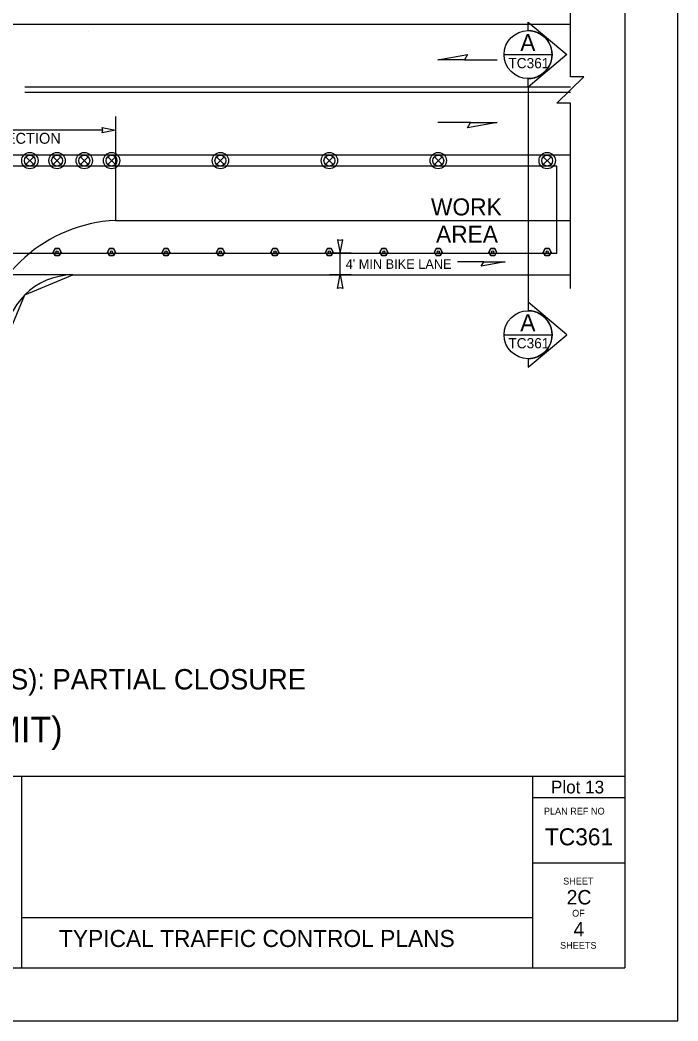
# Model space of a CAD drawing. Extents: x 99958 to 100176, y 99935 to 100011.
# Drawn here: x 100052.2 to 100056.06, y 99969.69 to 99975.57 of the extents above; entities that cross this region are included whole.
import ezdxf

# ---------------------------------------------------------------- set-up
doc = ezdxf.new("R2010")
doc.units = 0
for name, color, linetype in [('RD_ED_ShoulderPavedEdge', 7, 'Continuous'), ('RD_MK_LineDblYellowCenter', 7, 'Continuous'), ('RD_MK_LineEdgeWhite', 7, 'Continuous'), ('RD_MK_LineEdgeYellow', 7, 'Continuous'), ('RD_MK_LineLane', 7, 'Continuous'), ('SH_DE_DetailHeading1Text', 7, 'Continuous'), ('SH_DE_DetailHeading2Text', 7, 'Continuous'), ('SH_GI_PlotLimits', 7, 'Continuous'), ('SH_GI_SheetBorder', 7, 'Continuous'), ('SH_GI_SheetLocationText', 7, 'Continuous'), ('SH_GI_SheetTextInCells', 7, 'Continuous'), ('SH_GI_TitleBlockText', 7, 'Continuous'), ('SH_TI_WZSectionCut', 7, 'Continuous'), ('TR_WZ_TrafficSafetyDrum', 7, 'Continuous'), ('TR_WZ_TubularMarker', 7, 'Continuous'), ('TR_WZ_WorkAreaLabel', 7, 'Continuous'), ('TR_WZ_WorkZoneDetails', 7, 'Continuous'), ('TR_WZ_WorkZoneTextCurrent', 7, 'Continuous')]:
    doc.layers.add(name, color=color, linetype=linetype)

msp = doc.modelspace()

# ---------------------------------------------------------------- linework, layer by layer
at = {"layer": 'RD_ED_ShoulderPavedEdge'}
msp.add_line((100052.5069, 99974.0724), (100055.43, 99974.0724), dxfattribs=at)
msp.add_arc((100052.5069, 99973.6724), 0.4, 90, 180, dxfattribs=at)
at = {"layer": 'RD_MK_LineDblYellowCenter'}
for p, q in [((100055.43, 99975.1764), (100052.2245, 99975.1764)), ((100055.43, 99975.1444), (100052.2245, 99975.1444))]:
    msp.add_line(p, q, dxfattribs=at)
at = {"layer": 'RD_MK_LineEdgeWhite'}
msp.add_arc((100052.7969, 99973.5319), 0.8615, 92.65548, 170.6116, dxfattribs=at)
at = {"layer": 'RD_MK_LineEdgeYellow'}
msp.add_line((100052.7569, 99974.3924), (100055.43, 99974.3924), dxfattribs=at)
at = {"layer": 'RD_MK_LineLane'}
for points in [[(100055.43, 99975.5444), (100048.195, 99975.5444)], [(100055.43, 99974.7764), (100048.195, 99974.7764)]]:
    msp.add_lwpolyline(points, dxfattribs=at)
at = {"layer": 'SH_GI_PlotLimits'}
msp.add_lwpolyline([(100039.0625, 99969.6875), (100056.0625, 99969.6875), (100056.0625, 99980.6875), (100039.0625, 99980.6875)], close=True, dxfattribs=at)
at = {"layer": 'SH_GI_SheetBorder'}
for p, q in [((100055.75, 99980.375), (100055.75, 99970)), ((100040, 99971.1259), (100055.75, 99971.1259)), ((100052.2055, 99971.1259), (100052.2055, 99970)), ((100055.2079, 99971.1259), (100055.2079, 99970)), ((100055.2079, 99971.0008), (100055.75, 99971.0008)), ((100055.2079, 99970.6176), (100055.75, 99970.6176)), ((100052.2055, 99970.2955), (100055.2079, 99970.2955)), ((100040, 99970), (100055.75, 99970))]:
    msp.add_line(p, q, dxfattribs=at)
at = {"layer": 'SH_TI_WZSectionCut'}
for p, q in [((100055.1819, 99975.5088), (100055.1819, 99975.5587)), ((100055.1819, 99975.5587), (100055.41, 99975.3676)), ((100055.41, 99975.3676), (100055.1819, 99975.1764)), ((100055.1819, 99975.1764), (100055.1819, 99975.2264)), ((100055.1819, 99975.1764), (100055.1819, 99973.9125)), ((100055.1819, 99973.9125), (100055.1819, 99973.8625)), ((100055.41, 99973.7213), (100055.1819, 99973.9125)), ((100055.1819, 99973.5302), (100055.41, 99973.7213)), ((100055.1819, 99973.5801), (100055.1819, 99973.5302))]:
    msp.add_line(p, q, dxfattribs=at)
for points in [[(100055.0406, 99975.3676), (100055.3231, 99975.3676)], [(100055.0406, 99973.7213), (100055.3231, 99973.7213)]]:
    msp.add_lwpolyline(points, dxfattribs=at)
for centre in [(100055.1819, 99975.3676), (100055.1819, 99973.7213)]:
    msp.add_circle(centre, 0.1412, dxfattribs=at)
for centre in [(100055.1819, 99975.3676), (100055.1819, 99973.7213)]:
    msp.add_arc(centre, 0.1412, 269.99779, 90.00221, dxfattribs=at)
at = {"layer": 'TR_WZ_TrafficSafetyDrum'}
for p, q in [((100052.2313, 99974.7671), (100052.2765, 99974.7218)), ((100052.2765, 99974.7671), (100052.2313, 99974.7218)), ((100052.3913, 99974.7671), (100052.4365, 99974.7218)), ((100052.4365, 99974.7671), (100052.3913, 99974.7218)), ((100052.5513, 99974.7671), (100052.5965, 99974.7218)), ((100052.5965, 99974.7671), (100052.5513, 99974.7218)), ((100052.7113, 99974.7671), (100052.7565, 99974.7218)), ((100052.7565, 99974.7671), (100052.7113, 99974.7218)), ((100053.3513, 99974.7671), (100053.3965, 99974.7218)), ((100053.3965, 99974.7671), (100053.3513, 99974.7218)), ((100053.9913, 99974.7671), (100054.0365, 99974.7218)), ((100054.0365, 99974.7671), (100053.9913, 99974.7218)), ((100054.6313, 99974.7671), (100054.6765, 99974.7218)), ((100054.6765, 99974.7671), (100054.6313, 99974.7218)), ((100055.2713, 99974.7671), (100055.3165, 99974.7218)), ((100055.3165, 99974.7671), (100055.2713, 99974.7218))]:
    msp.add_line(p, q, dxfattribs=at)
for centre, radius in [((100052.2539, 99974.7445), 0.048), ((100052.2539, 99974.7445), 0.048), ((100052.2539, 99974.7445), 0.032), ((100052.4139, 99974.7445), 0.048), ((100052.4139, 99974.7445), 0.048), ((100052.4139, 99974.7445), 0.032), ((100052.5739, 99974.7445), 0.048), ((100052.5739, 99974.7445), 0.048), ((100052.5739, 99974.7445), 0.032), ((100052.7339, 99974.7445), 0.048), ((100052.7339, 99974.7445), 0.048), ((100052.7339, 99974.7445), 0.032), ((100053.3739, 99974.7445), 0.048), ((100053.3739, 99974.7445), 0.048), ((100053.3739, 99974.7445), 0.032), ((100054.0139, 99974.7445), 0.048), ((100054.0139, 99974.7445), 0.048), ((100054.0139, 99974.7445), 0.032), ((100054.6539, 99974.7445), 0.048), ((100054.6539, 99974.7445), 0.048), ((100054.6539, 99974.7445), 0.032), ((100055.2939, 99974.7445), 0.048), ((100055.2939, 99974.7445), 0.048), ((100055.2939, 99974.7445), 0.032)]:
    msp.add_circle(centre, radius, dxfattribs=at)
at = {"layer": 'TR_WZ_TubularMarker'}
for points in [[(100052.3908, 99974.2071), (100052.4024, 99974.2271), (100052.4255, 99974.2271), (100052.437, 99974.2071), (100052.4255, 99974.1871), (100052.4024, 99974.1871)], [(100052.7108, 99974.2071), (100052.7224, 99974.2271), (100052.7455, 99974.2271), (100052.757, 99974.2071), (100052.7455, 99974.1871), (100052.7224, 99974.1871)], [(100053.0308, 99974.2071), (100053.0424, 99974.2271), (100053.0655, 99974.2271), (100053.077, 99974.2071), (100053.0655, 99974.1871), (100053.0424, 99974.1871)], [(100053.3508, 99974.2071), (100053.3624, 99974.2271), (100053.3855, 99974.2271), (100053.397, 99974.2071), (100053.3855, 99974.1871), (100053.3624, 99974.1871)], [(100053.6708, 99974.2071), (100053.6824, 99974.2271), (100053.7055, 99974.2271), (100053.717, 99974.2071), (100053.7055, 99974.1871), (100053.6824, 99974.1871)], [(100053.9908, 99974.2071), (100054.0024, 99974.2271), (100054.0255, 99974.2271), (100054.037, 99974.2071), (100054.0255, 99974.1871), (100054.0024, 99974.1871)], [(100054.3108, 99974.2071), (100054.3224, 99974.2271), (100054.3455, 99974.2271), (100054.357, 99974.2071), (100054.3455, 99974.1871), (100054.3224, 99974.1871)], [(100054.6308, 99974.2071), (100054.6424, 99974.2271), (100054.6655, 99974.2271), (100054.677, 99974.2071), (100054.6655, 99974.1871), (100054.6424, 99974.1871)], [(100054.9508, 99974.2071), (100054.9624, 99974.2271), (100054.9855, 99974.2271), (100054.997, 99974.2071), (100054.9855, 99974.1871), (100054.9624, 99974.1871)], [(100055.2708, 99974.2071), (100055.2824, 99974.2271), (100055.3055, 99974.2271), (100055.317, 99974.2071), (100055.3055, 99974.1871), (100055.2824, 99974.1871)]]:
    msp.add_lwpolyline(points, close=True, dxfattribs=at)
for points in [[(100052.4024, 99974.1871), (100052.4255, 99974.1871), (100052.437, 99974.2071), (100052.4255, 99974.2271), (100052.4024, 99974.2271), (100052.3908, 99974.2071), (100052.4024, 99974.1871)], [(100052.7224, 99974.1871), (100052.7455, 99974.1871), (100052.757, 99974.2071), (100052.7455, 99974.2271), (100052.7224, 99974.2271), (100052.7108, 99974.2071), (100052.7224, 99974.1871)], [(100053.0424, 99974.1871), (100053.0655, 99974.1871), (100053.077, 99974.2071), (100053.0655, 99974.2271), (100053.0424, 99974.2271), (100053.0308, 99974.2071), (100053.0424, 99974.1871)], [(100053.3624, 99974.1871), (100053.3855, 99974.1871), (100053.397, 99974.2071), (100053.3855, 99974.2271), (100053.3624, 99974.2271), (100053.3508, 99974.2071), (100053.3624, 99974.1871)], [(100053.6824, 99974.1871), (100053.7055, 99974.1871), (100053.717, 99974.2071), (100053.7055, 99974.2271), (100053.6824, 99974.2271), (100053.6708, 99974.2071), (100053.6824, 99974.1871)], [(100054.0024, 99974.1871), (100054.0255, 99974.1871), (100054.037, 99974.2071), (100054.0255, 99974.2271), (100054.0024, 99974.2271), (100053.9908, 99974.2071), (100054.0024, 99974.1871)], [(100054.3224, 99974.1871), (100054.3455, 99974.1871), (100054.357, 99974.2071), (100054.3455, 99974.2271), (100054.3224, 99974.2271), (100054.3108, 99974.2071), (100054.3224, 99974.1871)], [(100054.6424, 99974.1871), (100054.6655, 99974.1871), (100054.677, 99974.2071), (100054.6655, 99974.2271), (100054.6424, 99974.2271), (100054.6308, 99974.2071), (100054.6424, 99974.1871)], [(100054.9624, 99974.1871), (100054.9855, 99974.1871), (100054.997, 99974.2071), (100054.9855, 99974.2271), (100054.9624, 99974.2271), (100054.9508, 99974.2071), (100054.9624, 99974.1871)], [(100055.2824, 99974.1871), (100055.3055, 99974.1871), (100055.317, 99974.2071), (100055.3055, 99974.2271), (100055.2824, 99974.2271), (100055.2708, 99974.2071), (100055.2824, 99974.1871)]]:
    msp.add_lwpolyline(points, dxfattribs=at)
for centre in [(100052.4139, 99974.2071), (100052.7339, 99974.2071), (100053.0539, 99974.2071), (100053.3739, 99974.2071), (100053.6939, 99974.2071), (100054.0139, 99974.2071), (100054.3339, 99974.2071), (100054.6539, 99974.2071), (100054.9739, 99974.2071), (100055.2939, 99974.2071)]:
    msp.add_circle(centre, 0.00667, dxfattribs=at)
at = {"layer": 'TR_WZ_WorkZoneDetails'}
for p, q in [((100052.5977, 99975.5006), (100052.5977, 99975.5006)), ((100054.8077, 99975.337), (100055.0006, 99975.337)), ((100052.7569, 99975.0036), (100052.7569, 99974.3924)), ((100054.8434, 99974.9684), (100054.6505, 99974.9684)), ((100052.682, 99974.9236), (100050.4119, 99974.9236)), ((100054.1419, 99974.2004), (100054.0139, 99974.2004)), ((100054.0779, 99974.0724), (100054.0779, 99974.2004)), ((100054.9207, 99974.1488), (100054.7664, 99974.1488)), ((100054.9207, 99974.1488), (100054.7664, 99974.1488)), ((100054.1419, 99974.0724), (100054.0139, 99974.0724))]:
    msp.add_line(p, q, dxfattribs=at)
msp.add_lwpolyline([(100055.43, 99973.9924), (100055.43, 99975.083), (100055.35, 99975.083), (100055.51, 99975.2379), (100055.43, 99975.2379), (100055.43, 99976.3285)], dxfattribs=at)
for points in [[(100054.6505, 99975.337), (100054.8256, 99975.3679), (100054.8077, 99975.337)], [(100055.0006, 99974.9684), (100054.8256, 99974.9376), (100054.8434, 99974.9684)], [(100052.7569, 99974.9236), (100052.6783, 99974.9082), (100052.682, 99974.9236), (100052.6783, 99974.9391)], [(100048.275, 99974.7114), (100048.275, 99974.2004), (100050.4939, 99974.2004), (100050.8139, 99974.2004), (100050.8139, 99974.2004), (100050.8139, 99974.2004), (100051.1339, 99974.2004), (100051.1339, 99974.2004), (100051.1339, 99974.2004), (100051.7739, 99974.2004), (100052.0939, 99974.2004), (100052.5069, 99974.2004), (100052.5069, 99974.2004), (100055.35, 99974.2004), (100055.35, 99974.7114)], [(100054.0779, 99974.2004), (100054.0933, 99974.2791), (100054.0779, 99974.2754), (100054.0625, 99974.2791)], [(100055.0464, 99974.1488), (100054.9064, 99974.1241), (100054.9207, 99974.1488)], [(100055.0464, 99974.1488), (100054.9064, 99974.1241), (100054.9207, 99974.1488)], [(100050.5869, 99974.0724), (100050.8698, 99973.9553), (100050.9869, 99973.6724), (100050.9869, 99972.4859), (100050.9869, 99972.4859), (100050.9869, 99972.4859), (100051.5269, 99972.4859), (100051.5269, 99972.4859), (100051.5269, 99972.4859), (100052.1069, 99972.4859), (100052.1069, 99973.6724), (100052.2241, 99973.9553), (100052.2241, 99973.9553), (100052.5069, 99974.0724), (100051.4539, 99974.0724)], [(100054.0779, 99974.0724), (100054.0933, 99973.9938), (100054.0779, 99973.9975), (100054.0625, 99973.9938)]]:
    msp.add_lwpolyline(points, close=True, dxfattribs=at)

# ---------------------------------------------------------------- texts
at = {"layer": 'SH_DE_DetailHeading1Text'}
msp.add_text('MULTILANE HIGHWAYS: SINGLE RIGHT LANE CLOSURE (45+ MPH, MAINTAIN EXISTING SPEED LIMIT)', height=0.15, rotation=360, dxfattribs=at).set_placement((100042.6439, 99971.3259))
at = {"layer": 'SH_DE_DetailHeading2Text'}
msp.add_text('AT-GRADE INTERSECTION (NO TURN LANES): PARTIAL CLOSURE', height=0.12, rotation=360, dxfattribs=at).set_placement((100048.7764, 99971.6359))
at = {"layer": 'SH_GI_SheetBorder'}
msp.add_text('PLAN REF NO', height=0.040032, dxfattribs=at).set_placement((100055.2747, 99970.9008))
at = {"layer": 'SH_GI_SheetLocationText'}
msp.add_text('Plot 13', height=0.075, dxfattribs=at).set_placement((100055.3164, 99971.025))
at = {"layer": 'SH_GI_SheetTextInCells'}
for s, p in [('SHEET', (100055.3877, 99970.4896)), ('OF', (100055.4406, 99970.3008)), ('SHEETS', (100055.3698, 99970.112))]:
    msp.add_text(s, height=0.04003, dxfattribs=at).set_placement(p)
at = {"layer": 'SH_GI_TitleBlockText'}
for s, height, p in [('TC361', 0.1, (100055.2803, 99970.72)), ('2C', 0.085, (100055.4084, 99970.3723)), ('4', 0.085, (100055.4485, 99970.1843)), ('TYPICAL TRAFFIC CONTROL PLANS', 0.1, (100052.4251, 99970.1224))]:
    msp.add_text(s, height=height, dxfattribs=at).set_placement(p)
at = {"layer": 'SH_TI_WZSectionCut'}
for s, height, rotation, p in [('A', 0.1, 0.00995, (100055.1356, 99975.3882)), ('TC361', 0.06, 360, (100055.066, 99975.2876)), ('A', 0.1, 0.00995, (100055.1356, 99973.7419)), ('TC361', 0.06, 360, (100055.066, 99973.6413))]:
    msp.add_text(s, height=height, rotation=rotation, dxfattribs=at).set_placement(p)
at = {"layer": 'TR_WZ_WorkAreaLabel'}
for s, p in [('WORK', (100054.611, 99974.4225)), ('AREA', (100054.6407, 99974.2624))]:
    msp.add_text(s, height=0.1, dxfattribs=at).set_placement(p)
at = {"layer": 'TR_WZ_WorkZoneTextCurrent'}
for s, height, p in [("20' DEVICE SPACING ACROSS INTERSECTION", 0.064, (100050.5269, 99974.8436)), ("4' MIN BIKE LANE", 0.056, (100054.1099, 99974.1084))]:
    msp.add_text(s, height=height, dxfattribs=at).set_placement(p)

doc.saveas('drawing.dxf')
